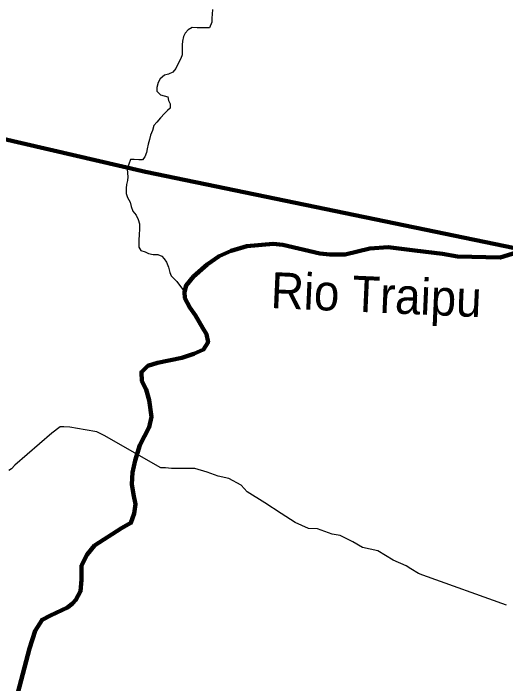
# Model space of a CAD drawing. Extents: x 553962 to 842807, y 8883888 to 9032388.
# Drawn here: x 722992 to 729831, y 8928988 to 8938306 of the extents above; entities that cross this region are included whole.
import ezdxf
from ezdxf.enums import TextEntityAlignment as Align

# ---------------------------------------------------------------- set-up
doc = ezdxf.new("R2010")
doc.units = 0
doc.header["$LTSCALE"] = 200
for name, color, linetype, lineweight in [('12', 7, 'Continuous', 25), ('24', 7, 'Continuous', 25), ('53', 7, 'Continuous', 106), ('9', 7, 'Continuous', 90)]:
    doc.layers.add(name, color=color, linetype=linetype, lineweight=lineweight)
doc.layers.add('49', color=7, linetype='Continuous')

msp = doc.modelspace()

# ---------------------------------------------------------------- linework, layer by layer
at = {"layer": '12'}
for points in [[(729842.6, 8930080), (728682.6, 8930494.7), (728621.5, 8930520.3), (728514.8, 8930581.6), (728448.7, 8930627.6), (728270.7, 8930704.3), (728057.2, 8930832.1), (727843.4, 8930878.3), (727706.2, 8930960.1), (727614.7, 8931006.1), (727533.3, 8931047), (727421.3, 8931067.6), (727217.8, 8931139.3), (727090.4, 8931144.6), (726907.3, 8931226.4), (726714.2, 8931354.1), (726485.5, 8931502.3), (726241.6, 8931655.6), (726155.3, 8931747.4), (725987.5, 8931839.4), (725834.8, 8931870.3), (725682.2, 8931926.6), (725514.3, 8931977.8), (725392, 8931978.1), (725274.8, 8931978.3), (725188.2, 8931978.4), (725106.8, 8931988.8), (725040.5, 8931988.9), (724252.6, 8932438.6), (724150.9, 8932489.8), (723987.9, 8932515.5), (723774.1, 8932551.6), (723692.6, 8932556.8), (723641.7, 8932556.9), (723524.2, 8932470.5)], [(723524.2, 8932470.5), (723013.1, 8932023.2), (722964.6, 8931975.3), (722928.4, 8931953)]]:
    msp.add_lwpolyline(points, dxfattribs=at)
at = {"layer": '24'}
for points in [[(725759.4, 8938360.9), (725753.9, 8938294.8), (725748.4, 8938238.8), (725748, 8938182.8), (725717, 8938106.6), (725544.1, 8938107.6), (725478, 8938108), (725421.8, 8938077.8), (725380.8, 8938032.2), (725355.1, 8937986.6), (725339.3, 8937920.5), (725339, 8937869.5), (725338.6, 8937818.6), (725338, 8937732.1), (725317.3, 8937681.2), (725276.1, 8937600), (725250.2, 8937539.1), (725207.8, 8937489.4), (725146.5, 8937460.6), (725092.5, 8937446.2), (725030.6, 8937397.8), (725004.8, 8937347.1), (724984, 8937275.9), (724983.6, 8937225), (725034.1, 8937173.8), (725084.8, 8937158.2), (725135.6, 8937147.7), (725145.5, 8937096.7), (725170.6, 8937050.7), (725170.1, 8936989.6), (725134.3, 8936954.2), (725093.3, 8936913.7), (725037, 8936852.9), (724985.7, 8936792.1), (724944.7, 8936746.5), (724923.9, 8936680.5), (724898, 8936614.4), (724882.3, 8936553.4), (724866.6, 8936487.3), (724850.9, 8936421.2), (724840.4, 8936370.3), (724819.6, 8936314.4), (724783.7, 8936268.8), (724732.8, 8936269.1), (724671.9, 8936274.6), (724621, 8936274.9)], [(724621, 8936274.9), (724573, 8936146.7), (724577.7, 8936085.6), (724582.4, 8936034.6), (724577, 8935983.7), (724561.3, 8935927.8), (724561, 8935876.9), (724560.4, 8935800.5), (724575.3, 8935744.4), (724615.6, 8935683), (724630.4, 8935621.8), (724650.3, 8935555.5), (724695.7, 8935499.2), (724725.8, 8935443), (724745.7, 8935381.8), (724745.2, 8935310.5), (724739.6, 8935229), (724734, 8935157.8), (724733.7, 8935106.9), (724733.3, 8935055.9), (724763.5, 8935009.9), (724824.4, 8934989.2), (724870, 8934968.5), (724936, 8934952.8), (724997.1, 8934952.5), (725052.8, 8934931.8), (725088.2, 8934895.9), (725118.4, 8934849.9), (725148.4, 8934778.4), (725163.2, 8934701.9), (725183.2, 8934656), (725223.6, 8934615), (725264, 8934579.1), (725368.5, 8934436.4)]]:
    msp.add_lwpolyline(points, dxfattribs=at)
at = {"layer": '24', "lineweight": 53}
for points in [[(726733.4, 8935086.7), (726602, 8935101.3), (726237.1, 8935072), (726018.1, 8935006.3), (725850.2, 8934933.2), (725682.3, 8934816.3), (725492.6, 8934648.3), (725390.4, 8934524.1), (725368.5, 8934436.4), (725375.8, 8934348.7), (725441.5, 8934217.2), (725521.8, 8934107.6), (725624, 8933932.2), (725675.1, 8933844.6), (725697, 8933734.9), (725631.3, 8933632.7), (725499.9, 8933574.2), (725332, 8933515.8), (724996.3, 8933450), (724857.6, 8933406.2), (724770, 8933318.5), (724777.3, 8933194.3), (724835.7, 8933077.4), (724879.5, 8932931.2), (724908.7, 8932697.4), (724879.5, 8932551.3), (724748.1, 8932302.9), (724682.4, 8932091), (724645.9, 8931922.9), (724638.6, 8931762.2), (724660.5, 8931616.1), (724689.7, 8931484.6), (724667.8, 8931353), (724624, 8931221.5), (724492.7, 8931148.4), (724120.4, 8930907.3), (724018.2, 8930783.1)], [(730163.7, 8935035.5), (729755, 8934911.3), (729163.8, 8934925.9), (728952.2, 8934962.4), (728571.5, 8935009.7), (728200.4, 8935057.4), (727944.9, 8935035.5), (727601.9, 8934955.1), (727390.2, 8934955.1), (727251.6, 8934969.8), (726733.4, 8935086.7)], [(724018.2, 8930783.1), (723938, 8930629.7), (723938, 8930432.4), (723924.2, 8930271.2), (723861.2, 8930151.4), (723813.9, 8930103.6), (723741.7, 8930044.3), (723507.3, 8929935.6), (723390.6, 8929877.1), (723295.7, 8929723.7), (723215.4, 8929475.3), (723055.5, 8928859.6)]]:
    msp.add_lwpolyline(points, dxfattribs=at)
at = {"layer": '53'}
for points in [[(726733.4, 8935086.7), (726602, 8935101.3), (726237.1, 8935072), (726018.1, 8935006.3), (725850.2, 8934933.2), (725682.3, 8934816.3), (725492.6, 8934648.3), (725390.4, 8934524.1), (725368.5, 8934436.4), (725375.8, 8934348.7), (725441.5, 8934217.2), (725521.8, 8934107.6), (725624, 8933932.2), (725675.1, 8933844.6), (725697, 8933734.9), (725631.3, 8933632.7), (725499.9, 8933574.2), (725332, 8933515.8), (724996.3, 8933450), (724857.6, 8933406.2), (724770, 8933318.5), (724777.3, 8933194.3), (724835.7, 8933077.4), (724879.5, 8932931.2), (724908.7, 8932697.4), (724879.5, 8932551.3), (724748.1, 8932302.9), (724682.4, 8932091), (724645.9, 8931922.9), (724638.6, 8931762.2), (724660.5, 8931616.1), (724689.7, 8931484.6), (724667.8, 8931353), (724624, 8931221.5), (724492.7, 8931148.4), (724120.4, 8930907.3), (724018.2, 8930783.1)], [(726733.4, 8935086.7), (726602, 8935101.3), (726237.1, 8935072), (726018.1, 8935006.3), (725850.2, 8934933.2), (725682.3, 8934816.3), (725492.6, 8934648.3), (725390.4, 8934524.1), (725368.5, 8934436.4), (725375.8, 8934348.7), (725441.5, 8934217.2), (725521.8, 8934107.6), (725624, 8933932.2), (725675.1, 8933844.6), (725697, 8933734.9), (725631.3, 8933632.7), (725499.9, 8933574.2), (725332, 8933515.8), (724996.3, 8933450), (724857.6, 8933406.2), (724770, 8933318.5), (724777.3, 8933194.3), (724835.7, 8933077.4), (724879.5, 8932931.2), (724908.7, 8932697.4), (724879.5, 8932551.3), (724748.1, 8932302.9), (724682.4, 8932091), (724645.9, 8931922.9), (724638.6, 8931762.2), (724660.5, 8931616.1), (724689.7, 8931484.6), (724667.8, 8931353), (724624, 8931221.5), (724492.7, 8931148.4), (724120.4, 8930907.3), (724018.2, 8930783.1)], [(726733.4, 8935086.7), (726602, 8935101.3), (726237.1, 8935072), (726018.1, 8935006.3), (725850.2, 8934933.2), (725682.3, 8934816.3), (725492.6, 8934648.3), (725390.4, 8934524.1), (725368.5, 8934436.4), (725375.8, 8934348.7), (725441.5, 8934217.2), (725521.8, 8934107.6), (725624, 8933932.2), (725675.1, 8933844.6), (725697, 8933734.9), (725631.3, 8933632.7), (725499.9, 8933574.2), (725332, 8933515.8), (724996.3, 8933450), (724857.6, 8933406.2), (724770, 8933318.5), (724777.3, 8933194.3), (724835.7, 8933077.4), (724879.5, 8932931.2), (724908.7, 8932697.4), (724879.5, 8932551.3), (724748.1, 8932302.9), (724682.4, 8932091), (724645.9, 8931922.9), (724638.6, 8931762.2), (724660.5, 8931616.1), (724689.7, 8931484.6), (724667.8, 8931353), (724624, 8931221.5), (724492.7, 8931148.4), (724120.4, 8930907.3), (724018.2, 8930783.1)], [(730163.7, 8935035.5), (729755, 8934911.3), (729163.8, 8934925.9), (728952.2, 8934962.4), (728571.5, 8935009.7), (728200.4, 8935057.4), (727944.9, 8935035.5), (727601.9, 8934955.1), (727390.2, 8934955.1), (727251.6, 8934969.8), (726733.4, 8935086.7)], [(730163.7, 8935035.5), (729755, 8934911.3), (729163.8, 8934925.9), (728952.2, 8934962.4), (728571.5, 8935009.7), (728200.4, 8935057.4), (727944.9, 8935035.5), (727601.9, 8934955.1), (727390.2, 8934955.1), (727251.6, 8934969.8), (726733.4, 8935086.7)], [(730163.7, 8935035.5), (729755, 8934911.3), (729163.8, 8934925.9), (728952.2, 8934962.4), (728571.5, 8935009.7), (728200.4, 8935057.4), (727944.9, 8935035.5), (727601.9, 8934955.1), (727390.2, 8934955.1), (727251.6, 8934969.8), (726733.4, 8935086.7)], [(724018.2, 8930783.1), (723938, 8930629.7), (723938, 8930432.4), (723924.2, 8930271.2), (723861.2, 8930151.4), (723813.9, 8930103.6), (723741.7, 8930044.3), (723507.3, 8929935.6), (723390.6, 8929877.1), (723295.7, 8929723.7), (723215.4, 8929475.3), (723055.5, 8928859.6)], [(724018.2, 8930783.1), (723938, 8930629.7), (723938, 8930432.4), (723924.2, 8930271.2), (723861.2, 8930151.4), (723813.9, 8930103.6), (723741.7, 8930044.3), (723507.3, 8929935.6), (723390.6, 8929877.1), (723295.7, 8929723.7), (723215.4, 8929475.3), (723055.5, 8928859.6)], [(724018.2, 8930783.1), (723938, 8930629.7), (723938, 8930432.4), (723924.2, 8930271.2), (723861.2, 8930151.4), (723813.9, 8930103.6), (723741.7, 8930044.3), (723507.3, 8929935.6), (723390.6, 8929877.1), (723295.7, 8929723.7), (723215.4, 8929475.3), (723055.5, 8928859.6)]]:
    msp.add_lwpolyline(points, dxfattribs=at)
at = {"layer": '9'}
for points in [[(696242, 8937672.8), (702061.8, 8937200.5), (702208.9, 8933124.7), (710319.1, 8936704.6), (716154, 8938115.2), (724825.2, 8936103.1), (730092.7, 8935013.9)], [(726733.4, 8935086.7), (726602, 8935101.3), (726237.1, 8935072), (726018.1, 8935006.3), (725850.2, 8934933.2), (725682.3, 8934816.3), (725492.6, 8934648.3), (725390.4, 8934524.1), (725368.5, 8934436.4), (725375.8, 8934348.7), (725441.5, 8934217.2), (725521.8, 8934107.6), (725624, 8933932.2), (725675.1, 8933844.6), (725697, 8933734.9), (725631.3, 8933632.7), (725499.9, 8933574.2), (725332, 8933515.8), (724996.3, 8933450), (724857.6, 8933406.2), (724770, 8933318.5), (724777.3, 8933194.3), (724835.7, 8933077.4), (724879.5, 8932931.2), (724908.7, 8932697.4), (724879.5, 8932551.3), (724748.1, 8932302.9), (724682.4, 8932091), (724645.9, 8931922.9), (724638.6, 8931762.2), (724660.5, 8931616.1), (724689.7, 8931484.6), (724667.8, 8931353), (724624, 8931221.5), (724492.7, 8931148.4), (724120.4, 8930907.3), (724018.2, 8930783.1)], [(730163.7, 8935035.5), (729755, 8934911.3), (729163.8, 8934925.9), (728952.2, 8934962.4), (728571.5, 8935009.7), (728200.4, 8935057.4), (727944.9, 8935035.5), (727601.9, 8934955.1), (727390.2, 8934955.1), (727251.6, 8934969.8), (726733.4, 8935086.7)], [(724018.2, 8930783.1), (723938, 8930629.7), (723938, 8930432.4), (723924.2, 8930271.2), (723861.2, 8930151.4), (723813.9, 8930103.6), (723741.7, 8930044.3), (723507.3, 8929935.6), (723390.6, 8929877.1), (723295.7, 8929723.7), (723215.4, 8929475.3), (723055.5, 8928859.6)]]:
    msp.add_lwpolyline(points, dxfattribs=at)

# ---------------------------------------------------------------- texts
at = {"layer": '49', "width": 0.95}
msp.add_text('Rio Traipu', height=500, rotation=357.482, dxfattribs=at).set_placement((728023.7, 8934146.6), align=Align.CENTER)

doc.saveas('drawing.dxf')
